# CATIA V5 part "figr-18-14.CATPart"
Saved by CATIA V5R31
Part number: Part1
Bounding box of the stored display mesh (mm): x -135 to 135, y -70 to 70, z 0 to 30
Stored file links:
  D:\PROJECTS\Project 2021\US EDITION\CATIA V5 6R 2021\Resources\Part Files\c18_catia_v6_6r2021_prt\figr-18-14.CATPart
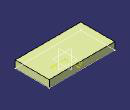
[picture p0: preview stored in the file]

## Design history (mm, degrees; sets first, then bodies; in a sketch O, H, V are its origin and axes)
Body1 (main body)
  Sketch1 on xy-plane, origin (0, 0, 0), H (1, 0, 0), V (0, 1, 0)
    line L1 (135, 70) -> (135, -70)
    line L2 (135, -70) -> (-135, -70)
    line L3 (-135, -70) -> (-135, 70)
    line L4 (-135, 70) -> (135, 70)
    length L2 = 270
    length L1 = 140
    vertical: L1 V, L3 V
    horizontal: L2 H, L4 H
    equidistance: L1 L3 O, L2 L4 O
  Extrude1: Element1 Sketch1, Lim1 30, Lim2 0
  DatumSurface1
